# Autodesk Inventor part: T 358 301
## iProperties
Created: 2006-03
Part Number: T 358 301
Material: 1.4301
Document SubType Name: Modeling
Designer: I.Baliuc
Manufacturer: Standard
Standards Organization: Custom
Description: Schaltscheibe
Density: 7.86 g/cm^3
Mass: 423.657 g
Surface Area: 131.517 cm^2
Volume: 53.9004 cm^3
Title: Schaltscheibe
Company: Mayer & Müller AG Schaltgeräte
HalbzeugNorm: DIN 671
Zweck: Trenner Haltevorrichtung
Abmessung: Rd 80
Author: T.Messerschmitt
Revision Number: 358301
Keywords: 380098
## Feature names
1. Bezeichnung2 [Tagging]
